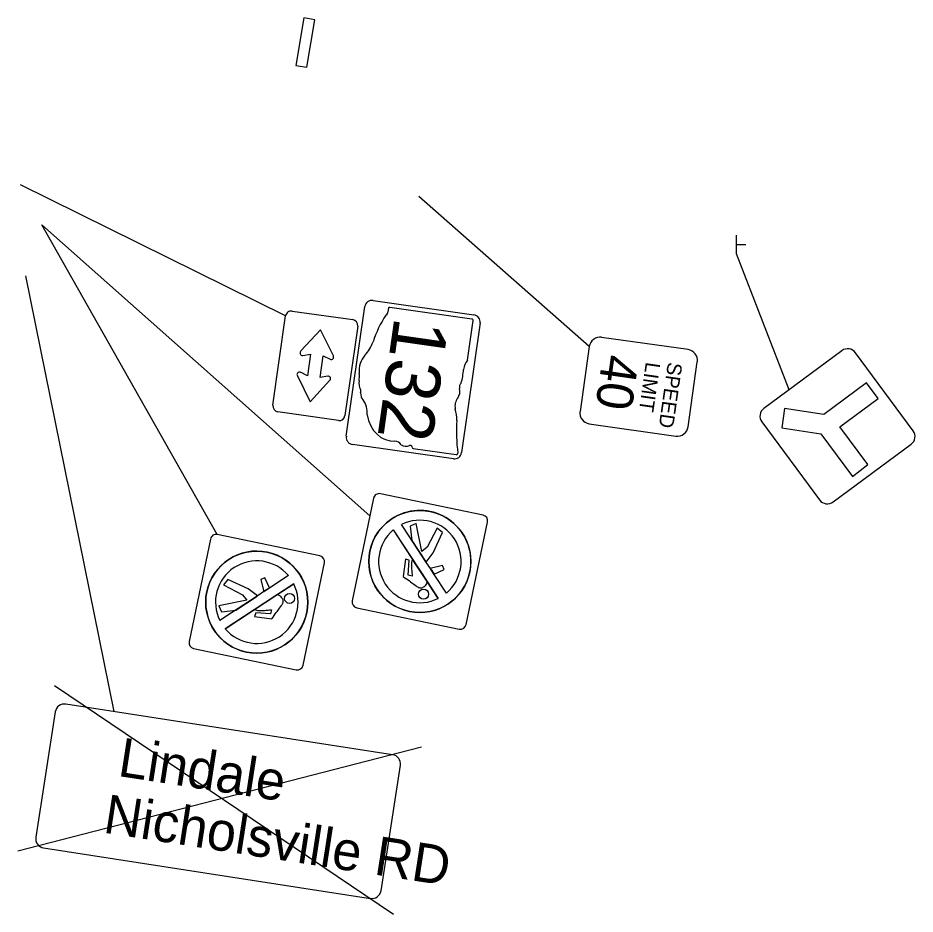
# Model space of a CAD drawing. Extents: x 1482113 to 1482447, y 365324 to 365634.
# Drawn here: x 1482293.2 to 1482447.3, y 365324.3 to 365478.3 of the extents above; entities that cross this region are included whole.
import ezdxf

# ---------------------------------------------------------------- set-up
doc = ezdxf.new("R2010")
doc.units = 0
for name, color, linetype in [('_CIVIL_CONSTRUCTION', 7, 'Continuous'), ('RS_Raster1', 7, 'Continuous'), ('RW_X_CL_500_Bearings', 7, 'Continuous'), ('SC_Scratch1', 7, 'Continuous')]:
    doc.layers.add(name, color=color, linetype=linetype)

msp = doc.modelspace()

# ---------------------------------------------------------------- linework, layer by layer
at = {"layer": '_CIVIL_CONSTRUCTION'}
msp.add_lwpolyline([(1482342.79, 365469.81), (1482344.17, 365477.96), (1482342.26, 365478.29), (1482340.89, 365470.13)], close=True, dxfattribs=at)
at = {"layer": 'RS_Raster1'}
for p, q in [((1482339.16, 365427.07), (1482293.62, 365449.63)), ((1482391.31, 365421.81), (1482362.04, 365447.63)), ((1482416.59, 365437.75), (1482416.59, 365440.95)), ((1482416.59, 365439.35), (1482418.19, 365439.35)), ((1482425.64, 365414.4), (1482416.59, 365437.75)), ((1482309.73, 365359.09), (1482294.52, 365433.98)), ((1482371.16, 365426.54), (1482357.07, 365428.54)), ((1482336.98, 365411.72), (1482339.16, 365427.07)), ((1482340.29, 365427.92), (1482350.69, 365426.44)), ((1482351.53, 365425.31), (1482349.35, 365409.96)), ((1482370.4, 365419.48), (1482371.37, 365426.28)), ((1482345.14, 365424.7), (1482341.79, 365421.06)), ((1482347.37, 365420.2), (1482345.14, 365424.7)), ((1482342.11, 365420.31), (1482343.44, 365420.53)), ((1482343.44, 365420.53), (1482342.91, 365416.81)), ((1482345.07, 365416.5), (1482345.6, 365420.22)), ((1482345.6, 365420.22), (1482346.82, 365419.64)), ((1482342.91, 365416.81), (1482341.69, 365417.39)), ((1482341.18, 365416.76), (1482343.37, 365412.33)), ((1482343.37, 365412.33), (1482346.77, 365416.02)), ((1482346.4, 365416.72), (1482345.07, 365416.5)), ((1482348.22, 365409.11), (1482337.82, 365410.59)), ((1482361.08, 365404.3), (1482368.45, 365403.25)), ((1482361.08, 365404.3), (1482361.08, 365404.3)), ((1482357.54, 365351.69), (1482301.4, 365360.38)), ((1482299.58, 365359.04), (1482296.24, 365337.5)), ((1482355.54, 365328.32), (1482358.87, 365349.86)), ((1482297.58, 365335.67), (1482353.71, 365326.98))]:
    msp.add_line(p, q, dxfattribs=at)
for points in [[(1482354.17, 365429.75), (1482371.49, 365427.28)], [(1482349.58, 365406.41), (1482352.75, 365428.68)], [(1482372.55, 365425.87), (1482369.38, 365403.59)], [(1482408.28, 365421.29), (1482393.43, 365423.4)], [(1482391.31, 365421.81), (1482389.72, 365410.67)], [(1482434.7, 365421.11), (1482421.3, 365411.19)], [(1482446.95, 365407.36), (1482437.03, 365420.76)], [(1482408.29, 365408.03), (1482409.87, 365419.17)], [(1482391.32, 365408.55), (1482406.17, 365406.44)], [(1482420.95, 365408.86), (1482430.87, 365395.47)], [(1482367.97, 365402.53), (1482350.64, 365405)], [(1482433.2, 365395.12), (1482446.6, 365405.03)]]:
    msp.add_lwpolyline(points, dxfattribs=at)
msp.add_lwpolyline([(1482424.86, 365411.16), (1482424.36, 365407.86), (1482431.1, 365406.85), (1482436.53, 365399.51), (1482439.18, 365401.54), (1482434.36, 365408.05), (1482440.91, 365412.9), (1482438.93, 365415.58), (1482431.59, 365410.15)], close=True, dxfattribs=at)
for centre, radius, start, end in [((1482353.99, 365428.51), 1.25, 81.9, 171.9), ((1482340.15, 365426.93), 1, 81.9, 171.9), ((1482371.31, 365426.04), 1.25, 351.9, 81.9), ((1482350.54, 365425.45), 1, 351.9, 81.9), ((1482393.17, 365421.55), 1.88, 81.9, 171.9), ((1482342.04, 365420.72), 0.417, 126.8904, 279.1046), ((1482408.02, 365419.43), 1.88, 351.9, 81.9), ((1482435.69, 365419.77), 1.67, 36.5, 126.5), ((1482346.99, 365420.02), 0.417, 244.6954, 26.4888), ((1482341.52, 365417.01), 0.417, 64.6954, 216.9096), ((1482346.47, 365416.31), 0.417, 317.3112, 99.1046), ((1482337.97, 365411.58), 1, 171.9, 261.9), ((1482422.29, 365409.85), 1.67, 126.5, 216.5), ((1482348.36, 365410.1), 1, 261.9, 351.9), ((1482391.58, 365410.41), 1.88, 171.9, 261.9), ((1482406.43, 365408.3), 1.88, 261.9, 351.9), ((1482445.61, 365406.37), 1.67, 306.5, 36.5), ((1482350.82, 365406.23), 1.25, 171.9, 261.9), ((1482368.14, 365403.77), 1.25, 261.9, 351.9), ((1482432.21, 365396.46), 1.67, 216.5, 306.5), ((1482301.16, 365358.8), 1.6, 81.2, 171.2), ((1482357.29, 365350.11), 1.6, 351.2, 81.2), ((1482297.82, 365337.25), 1.6, 171.2, 261.2), ((1482353.96, 365328.56), 1.6, 261.2, 351.2)]:
    msp.add_arc(centre, radius, start, end, dxfattribs=at)
for centre, major_axis, start_param, end_param in [((1482358.44, 365428.03), (-0.29, -2.07), 4.665946, 4.897461), ((1482357, 365428.28), (-0.039, -0.271), 3.00124, 4.508301), ((1482367.47, 365416.7), (-2.53, -17.77), 4.195997, 4.488961), ((1482356.16, 365427.93), (-0.106, -0.746), 0.519207, 1.627899), ((1482371.15, 365426.27), (-0.038, -0.269), 1.712693, 3.28349), ((1482350.05, 365424.59), (-0.79, -5.56), 0.823519, 1.323587), ((1482354.64, 365417.8), (-0.5, -3.53), 4.026481, 4.996735), ((1482371.81, 365417.63), (-0.37, -2.61), 4.042523, 4.731795), ((1482362.14, 365418.12), (-1.33, -9.36), 1.404758, 1.657858), ((1482353.26, 365415.65), (-0.27, -1.88), 4.691044, 5.507374), ((1482349.48, 365416.45), (-0.41, -2.9), 1.495662, 1.94098), ((1482351.65, 365414.15), (-0.075, -0.529), 1.147584, 2.315152), ((1482367.82, 365414.02), (-0.22, -1.56), 0.950623, 2.079405), ((1482369.61, 365414.89), (-0.107, -0.752), 3.836095, 5.185415), ((1482353.62, 365414.1), (-0.28, -1.99), 4.937069, 5.64225), ((1482350.43, 365410.2), (-0.48, -3.37), 1.647645, 2.488434), ((1482369.77, 365411.68), (-0.27, -1.88), 4.081561, 5.145723), ((1482364.53, 365409.04), (-0.7, -4.95), 1.699011, 2.107814), ((1482358.04, 365411.76), (-0.88, -6.15), 5.101752, 6.440018), ((1482388.49, 365408.83), (-3.5, -24.61), 4.814394, 5.042369), ((1482357.86, 365403.81), (-0.25, -1.75), 2.387724, 3.262537), ((1482359.98, 365407.11), (-0.34, -2.4), 5.934695, 6.695948), ((1482360.55, 365404.44), (-0.057, -0.4), 1.883978, 3.671073), ((1482361.09, 365404.58), (-0.039, -0.276), 5.05454, 6.418171), ((1482368.52, 365403.5), (-0.037, -0.258), 6.141152, 7.989035)]:
    msp.add_ellipse(centre, major_axis=major_axis, ratio=0.8, start_param=start_param, end_param=end_param, dxfattribs=at)
at = {"layer": 'RW_X_CL_500_Bearings'}
for p, q in [((1482327.42, 365389.52), (1482297.3, 365442.72)), ((1482297.3, 365442.72), (1482353.63, 365392.72)), ((1482361.56, 365391.43), (1482360.56, 365390.95)), ((1482361.56, 365391.43), (1482360.56, 365390.95)), ((1482362.57, 365386.61), (1482361.56, 365391.43)), ((1482362.57, 365386.61), (1482361.56, 365391.43)), ((1482365.37, 365378.54), (1482357.66, 365390.33)), ((1482360.56, 365390.95), (1482360.86, 365388.49)), ((1482360.56, 365390.95), (1482360.86, 365388.49)), ((1482365.2, 365390.59), (1482363.45, 365387.35)), ((1482365.2, 365390.59), (1482363.45, 365387.35)), ((1482364.51, 365386.35), (1482366.1, 365389.88)), ((1482364.51, 365386.35), (1482366.1, 365389.88)), ((1482366.1, 365389.88), (1482365.2, 365390.59)), ((1482366.1, 365389.88), (1482365.2, 365390.59)), ((1482360.86, 365388.49), (1482363.25, 365384.84)), ((1482363.45, 365387.35), (1482362.57, 365386.61)), ((1482363.45, 365387.35), (1482362.57, 365386.61)), ((1482359.74, 365385.27), (1482359.36, 365382.3)), ((1482359.74, 365385.27), (1482359.36, 365382.3)), ((1482360.36, 365385.09), (1482359.74, 365385.27)), ((1482360.36, 365385.09), (1482359.74, 365385.27)), ((1482360.2, 365382.53), (1482360.36, 365385.09)), ((1482360.2, 365382.53), (1482360.36, 365385.09)), ((1482363.47, 365381.44), (1482360.97, 365385.25)), ((1482363.3, 365384.77), (1482363.66, 365385.21)), ((1482363.3, 365384.77), (1482363.66, 365385.21)), ((1482363.66, 365385.21), (1482364.51, 365386.35)), ((1482363.66, 365385.21), (1482364.51, 365386.35)), ((1482363.25, 365384.84), (1482363.3, 365384.77)), ((1482366.12, 365384.17), (1482364.01, 365383.68)), ((1482366.12, 365384.17), (1482364.01, 365383.68)), ((1482364.01, 365383.68), (1482364.14, 365383.49)), ((1482364.65, 365382.7), (1482366.4, 365383.52)), ((1482364.65, 365382.7), (1482366.4, 365383.52)), ((1482366.4, 365383.52), (1482366.12, 365384.17)), ((1482366.4, 365383.52), (1482366.12, 365384.17)), ((1482329.22, 365381.78), (1482328.51, 365380.88)), ((1482329.22, 365381.78), (1482328.51, 365380.88)), ((1482332.74, 365380.2), (1482329.22, 365381.78)), ((1482332.74, 365380.2), (1482329.22, 365381.78)), ((1482335.57, 365382.08), (1482334.92, 365381.8)), ((1482335.57, 365382.08), (1482334.92, 365381.8)), ((1482334.92, 365381.8), (1482335.41, 365379.69)), ((1482334.92, 365381.8), (1482335.41, 365379.69)), ((1482336.39, 365380.34), (1482335.57, 365382.08)), ((1482336.39, 365380.34), (1482335.57, 365382.08)), ((1482359.36, 365382.3), (1482359.37, 365382.29)), ((1482359.36, 365382.3), (1482359.37, 365382.29)), ((1482360.91, 365382.35), (1482360.2, 365382.53)), ((1482360.91, 365382.35), (1482360.2, 365382.53)), ((1482328.51, 365380.88), (1482331.75, 365379.14)), ((1482328.51, 365380.88), (1482331.75, 365379.14)), ((1482340.56, 365381.05), (1482328.77, 365373.34)), ((1482363.55, 365381.31), (1482363.47, 365381.44)), ((1482330.61, 365376.54), (1482334.26, 365378.94)), ((1482331.75, 365379.14), (1482332.49, 365378.25)), ((1482331.75, 365379.14), (1482332.49, 365378.25)), ((1482333.88, 365379.35), (1482332.74, 365380.2)), ((1482333.88, 365379.35), (1482332.74, 365380.2)), ((1482337.66, 365379.15), (1482333.85, 365376.66)), ((1482334.33, 365378.98), (1482333.88, 365379.35)), ((1482334.33, 365378.98), (1482333.88, 365379.35)), ((1482334.26, 365378.94), (1482334.33, 365378.98)), ((1482335.41, 365379.69), (1482335.61, 365379.82)), ((1482337.78, 365379.23), (1482337.66, 365379.15)), ((1482332.49, 365378.25), (1482327.67, 365377.25)), ((1482332.49, 365378.25), (1482327.67, 365377.25)), ((1482327.67, 365377.25), (1482328.15, 365376.24)), ((1482327.67, 365377.25), (1482328.15, 365376.24)), ((1482328.15, 365376.24), (1482330.61, 365376.54)), ((1482328.15, 365376.24), (1482330.61, 365376.54)), ((1482334.01, 365376.04), (1482333.82, 365375.43)), ((1482334.01, 365376.04), (1482333.82, 365375.43)), ((1482336.56, 365375.88), (1482334.01, 365376.04)), ((1482336.56, 365375.88), (1482334.01, 365376.04)), ((1482336.74, 365376.59), (1482336.56, 365375.88)), ((1482336.74, 365376.59), (1482336.56, 365375.88)), ((1482333.82, 365375.43), (1482336.8, 365375.04)), ((1482333.82, 365375.43), (1482336.8, 365375.04)), ((1482336.8, 365375.04), (1482336.8, 365375.06)), ((1482336.8, 365375.04), (1482336.8, 365375.06))]:
    msp.add_line(p, q, dxfattribs=at)
for points in [[(1482354.26, 365395.76), (1482350.59, 365378.14)], [(1482373.07, 365392.86), (1482355.45, 365396.53)], [(1482364.14, 365383.49), (1482363.25, 365384.84), (1482360.38, 365389.22), (1482359.05, 365391.24)], [(1482370.17, 365374.05), (1482373.84, 365391.67)], [(1482345.04, 365385.85), (1482327.42, 365389.52)], [(1482357.65, 365390.32), (1482360.71, 365385.65), (1482360.71, 365385.65), (1482360.71, 365385.65), (1482363.47, 365381.44), (1482363.47, 365381.44)], [(1482326.24, 365388.75), (1482322.56, 365371.13)], [(1482342.14, 365367.05), (1482345.82, 365384.67)], [(1482366.78, 365379.46), (1482364.68, 365382.67), (1482364.13, 365383.48), (1482364.14, 365383.49)], [(1482364.14, 365383.49), (1482364.65, 365382.7), (1482364.65, 365382.7)], [(1482339.63, 365382.46), (1482336.43, 365380.36), (1482335.61, 365379.82), (1482335.61, 365379.82)], [(1482335.61, 365379.82), (1482336.39, 365380.34), (1482336.39, 365380.34)], [(1482337.66, 365379.15), (1482340.56, 365381.05)], [(1482363.47, 365381.44), (1482365.37, 365378.54)], [(1482363.47, 365381.44), (1482363.47, 365381.44)], [(1482335.61, 365379.82), (1482334.26, 365378.94), (1482329.87, 365376.06), (1482327.85, 365374.74)], [(1482328.77, 365373.33), (1482333.45, 365376.39), (1482333.45, 365376.4), (1482333.45, 365376.4), (1482337.66, 365379.15), (1482337.66, 365379.15)], [(1482337.66, 365379.15), (1482337.66, 365379.15)], [(1482351.36, 365376.95), (1482368.98, 365373.28)], [(1482323.34, 365369.95), (1482340.96, 365366.27)]]:
    msp.add_lwpolyline(points, dxfattribs=at)
for centre, radius in [((1482362.21, 365384.89), 8.77), ((1482334.2, 365377.9), 8.77), ((1482339.83, 365378.54), 0.864), ((1482362.85, 365379.27), 0.864)]:
    msp.add_circle(centre, radius, dxfattribs=at)
for centre, radius, start, end in [((1482355.24, 365395.55), 1, 78.219, 168.219), ((1482362.21, 365384.89), 8.77, 348.219, 168.219), ((1482372.86, 365391.88), 1, 348.219, 78.219), ((1482362.21, 365384.89), 7.09, 310.0669, 116.4669), ((1482362.21, 365384.89), 7.09, 310.0669, 116.4669), ((1482327.22, 365388.55), 1, 78.219, 168.219), ((1482362.21, 365384.89), 7.09, 130.038, 296.3903), ((1482362.21, 365384.89), 7.09, 130.038, 296.3903), ((1482334.2, 365377.9), 8.77, 78.219, 258.219), ((1482334.2, 365377.9), 8.77, 258.219, 78.219), ((1482362.21, 365384.89), 8.77, 168.219, 348.219), ((1482334.2, 365377.9), 7.09, 40.0669, 206.4669), ((1482334.2, 365377.9), 7.09, 40.0669, 206.4669), ((1482344.84, 365384.87), 1, 348.219, 78.219), ((1482334.2, 365377.9), 7.09, 220.038, 26.3903), ((1482334.2, 365377.9), 7.09, 220.038, 26.3903), ((1482362.48, 365382.61), 1.54, 310.2941, 310.3473), ((1482336.49, 365378.16), 1.54, 40.2941, 40.3473), ((1482351.57, 365377.93), 1, 168.219, 258.219), ((1482369.19, 365374.26), 1, 258.219, 348.219), ((1482323.54, 365370.92), 1, 168.219, 258.219), ((1482341.16, 365367.25), 1, 258.219, 348.219)]:
    msp.add_arc(centre, radius, start, end, dxfattribs=at)
for points in [[(1482360.97, 365385.25), (1482360.93, 365385.19), (1482360.82, 365385), (1482360.76, 365384.54), (1482360.76, 365384.12), (1482360.81, 365383.37), (1482360.85, 365382.85), (1482360.91, 365382.35)], [(1482360.97, 365385.25), (1482360.93, 365385.19), (1482360.82, 365385), (1482360.76, 365384.54), (1482360.76, 365384.12), (1482360.81, 365383.37), (1482360.85, 365382.85), (1482360.91, 365382.35)], [(1482359.37, 365382.29), (1482360.16, 365381.73), (1482361.39, 365380.83), (1482361.84, 365380.5), (1482362, 365380.43), (1482362.16, 365380.39), (1482362.56, 365380.31), (1482363.15, 365380.67), (1482363.39, 365381.07), (1482363.55, 365381.31)], [(1482359.37, 365382.29), (1482360.16, 365381.73), (1482361.39, 365380.83), (1482361.84, 365380.5), (1482362, 365380.43), (1482362.16, 365380.39), (1482362.56, 365380.31), (1482363.15, 365380.67), (1482363.39, 365381.07), (1482363.55, 365381.31)], [(1482336.8, 365375.06), (1482337.36, 365375.84), (1482338.27, 365377.07), (1482338.6, 365377.52), (1482338.67, 365377.68), (1482338.7, 365377.85), (1482338.78, 365378.24), (1482338.42, 365378.83), (1482338.02, 365379.07), (1482337.78, 365379.23)], [(1482336.8, 365375.06), (1482337.36, 365375.84), (1482338.27, 365377.07), (1482338.6, 365377.52), (1482338.67, 365377.68), (1482338.7, 365377.85), (1482338.78, 365378.24), (1482338.42, 365378.83), (1482338.02, 365379.07), (1482337.78, 365379.23)], [(1482333.85, 365376.66), (1482333.91, 365376.61), (1482334.1, 365376.5), (1482334.55, 365376.44), (1482334.98, 365376.44), (1482335.72, 365376.49), (1482336.25, 365376.54), (1482336.74, 365376.59)], [(1482333.85, 365376.66), (1482333.91, 365376.61), (1482334.1, 365376.5), (1482334.55, 365376.44), (1482334.98, 365376.44), (1482335.72, 365376.49), (1482336.25, 365376.54), (1482336.74, 365376.59)]]:
    msp.add_open_spline(points, degree=3, dxfattribs=at)
at = {"layer": 'SC_Scratch1'}
for p, q in [((1482299.45, 365363.55), (1482357.7, 365324.3)), ((1482362.5, 365352.96), (1482293.17, 365335.1))]:
    msp.add_line(p, q, dxfattribs=at)

# ---------------------------------------------------------------- texts
at = {"layer": 'RS_Raster1'}
for s, height, rotation, p in [('132', 9.375, 261.9, (1482357.88, 365427.08)), ('40', 6.25, 261.9, (1482393.67, 365420.66)), ('LIMIT', 2.5, 261.9, (1482401.04, 365419.24)), ('SPEED', 2.5, 261.9, (1482404.83, 365419.22)), ('Lindale', 6.667, 351.2, (1482310.16, 365348.06)), ('       Nicholsville RD', 6.667, 351.2, (1482290.51, 365340.98))]:
    msp.add_text(s, height=height, rotation=rotation, dxfattribs=at).set_placement(p)

doc.saveas('drawing.dxf')
